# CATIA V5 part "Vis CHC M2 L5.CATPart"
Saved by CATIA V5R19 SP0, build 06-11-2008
Part number: Vis CHC M2 L5
Revision: ANY
Definition: UNKNOWN
Nomenclature: Vis CHC
Source: Unknown
Bounding box of the stored display mesh (mm): x -1.899 to 1.899, y -44.29 to -37.29, z -1.9 to 1.9
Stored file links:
  C:\Users\Rémi\Documents\BTS CPI\Projet 04- Guitar Elec\Maquette 3D\Moteur\Vis CHC.CATPart
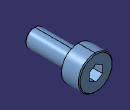
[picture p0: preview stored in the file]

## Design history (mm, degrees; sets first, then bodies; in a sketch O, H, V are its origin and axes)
Body1 "Enlèv. mat.-Extru.1" (main body)
  Solid1: solid without history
